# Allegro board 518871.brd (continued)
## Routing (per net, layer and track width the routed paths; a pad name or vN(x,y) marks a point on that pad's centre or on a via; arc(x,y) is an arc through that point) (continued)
H_DDR1_A12: length 100.4
  TOP w0.102: U29.N7 v2(11.11,76.11)
  TOP w0.127: v2(11.11,90.33) U23.N7 11.51,92.01 12.22,92.71 21.17,92.71 23.02,94.56 23.02,98.43 23.16,98.57 23.77,98.57 23.89,98.7 23.89,99.51 24.02,99.64 24.27,99.64 24.4,99.51 24.4,98.7 24.53,98.57 24.78,98.57 24.91,98.7 24.91,99.51 25.04,99.64 25.29,99.64 25.42,99.51 25.42,98.7 25.54,98.57 25.8,98.57 25.93,98.7 25.93,99.51 26.05,99.64 26.31,99.64 26.43,99.51 26.43,98.7 26.56,98.57 26.81,98.57 26.94,98.7 26.94,99.51 27.07,99.64 27.32,99.64 27.45,99.51 27.45,98.7 27.58,98.57 27.83,98.57 27.96,98.7 27.96,99.51 28.08,99.64 28.34,99.64 28.47,99.51 28.47,98.7 28.59,98.57 28.85,98.57 28.97,98.7 28.97,99.51 29.1,99.64 29.35,99.64 29.48,99.51 29.48,98.7 29.61,98.57 29.86,98.57 29.99,98.7 29.99,99.51 30.12,99.64 30.37,99.64 30.5,99.51 30.5,98.7 30.62,98.57 30.88,98.57 31.01,98.7 31.01,99.51 31.13,99.64 31.39,99.64 31.51,99.51 31.51,98.7 31.64,98.57 31.89,98.57 32.02,98.7 32.02,99.51 32.15,99.64 32.4,99.64 32.53,99.51 32.53,98.7 32.66,98.57 32.91,98.57 33.04,98.7 33.04,99.51 33.16,99.64 33.42,99.64 33.55,99.51 33.55,98.7 33.67,98.57 33.93,98.57 34.05,98.7 34.05,99.51 34.18,99.64 34.43,99.64 34.56,99.51 34.56,98.7 34.69,98.57 34.94,98.57 35.07,98.7 35.07,99.51 35.2,99.64 35.45,99.64 35.58,99.51 35.58,98.7 35.7,98.57 35.96,98.57 36.09,98.7 36.09,99.51 36.21,99.64 36.47,99.64 36.59,99.51 36.59,98.7 36.72,98.57 36.97,98.57 37.1,98.7 37.1,99.51 37.23,99.64 37.48,99.64 37.61,99.51 37.61,98.7 37.74,98.57 37.99,98.57 38.12,98.7 38.12,99.51 38.24,99.64 38.5,99.64 38.63,99.51 38.63,98.7 38.75,98.57 39.01,98.57 39.13,98.7 39.13,99.51 39.26,99.64 39.51,99.64 39.64,99.51 39.64,98.7 39.77,98.57 40.49,98.57 40.74,98.32 40.74,98.02 40.22,97.5 40.22,97.01 40.55,96.68 41.11,96.68 v1(41.3,96.88) ; U27.AC22 v3(43.35,88.87)
  LY3 w0.133: v1(41.3,96.88) 41.3,96.37 43.35,94.31 v3(43.35,88.87)
  LY4 w0.133: v2(11.11,90.33) 11.51,89.71 11.51,88.49 11.24,87.47 11.24,86.56 11.51,82.73 11.51,76.5 v2(11.11,76.11) 11.51,75.71 11.51,73.74 11.18,73.41 11.18,72.64 12.06,71.75 v1(12.06,70.36)
  BOTTOM w0.127: v1(12.06,70.36) R282.2
H_DDR1_A13: length 99
  TOP w0.102: U29.T3 v2(8.71,80.1) ; U23.T3 v2(8.71,94.33)
  TOP w0.127: U27.AC15 v3(48.55,88.87) ; R83.2 v1(4.7,69.91)
  LY3 w0.133: v1(4.7,69.91) 4.7,75.64 8.71,79.66 v2(8.71,80.1) 6.48,80.1 5.99,80.59 5.99,93.98 6.76,94.74 8.3,94.74 v2(8.71,94.33)
  LY4 w0.133: v2(8.71,94.33) 9.12,94.73 9.12,97.79 10.09,98.76 24.4,98.76 26.14,100.5 26.49,100.5 26.63,100.37 26.63,99.51 26.76,99.38 27.03,99.38 27.16,99.51 27.16,100.37 27.29,100.5 27.56,100.5 27.69,100.37 27.69,99.51 27.83,99.38 28.09,99.38 28.23,99.51 28.23,100.37 28.36,100.5 28.63,100.5 28.76,100.37 28.76,99.51 28.89,99.38 29.16,99.38 29.29,99.51 29.29,100.37 29.43,100.5 29.69,100.5 29.83,100.37 29.83,99.51 29.96,99.38 30.23,99.38 30.36,99.51 30.36,100.37 30.49,100.5 30.76,100.5 30.89,100.37 30.89,99.51 31.03,99.38 31.29,99.38 31.43,99.51 31.43,100.37 31.56,100.5 31.83,100.5 31.96,100.37 31.96,99.6 32.09,99.47 32.51,99.47 32.64,99.6 32.64,99.95 33.19,100.5 42.63,100.5 43.94,99.2 44.6,99.2 44.72,99.32 45.57,99.32 48.39,96.5 48.39,92.46 47.77,91.84 47.77,90.03 48.55,89.24 v3(48.55,88.87)
H_DDR1_A14: length 100.1
  TOP w0.102: U29.T7 v2(8.71,76.11) ; U23.T7 v2(8.71,90.33)
  TOP w0.127: v1(41.66,99.64) 40.19,101.11 36.3,101.11 36.18,101.23 36.18,101.73 36.05,101.85 35.79,101.85 35.67,101.73 35.67,101.23 35.54,101.11 35.29,101.11 35.16,101.23 35.16,101.73 35.03,101.85 34.78,101.85 34.65,101.73 34.65,101.23 34.52,101.11 34.27,101.11 34.14,101.23 34.14,101.73 34.02,101.85 33.76,101.85 33.64,101.73 33.64,101.23 33.51,101.11 33.25,101.11 33.13,101.23 33.13,101.73 33,101.85 32.75,101.85 32.62,101.73 32.62,101.23 32.49,101.11 32.24,101.11 32.11,101.23 32.11,101.73 31.98,101.85 31.73,101.85 31.6,101.73 31.6,101.23 31.48,101.11 31.22,101.11 31.1,101.23 31.1,101.73 30.97,101.85 30.71,101.85 30.59,101.73 30.59,101.23 30.46,101.11 30.21,101.11 30.08,101.23 30.08,101.73 29.95,101.85 29.7,101.85 29.57,101.73 29.57,101.23 29.44,101.11 29.19,101.11 29.06,101.23 29.06,101.73 28.94,101.85 28.68,101.85 28.56,101.73 28.56,101.23 28.43,101.11 28.17,101.11 28.05,101.23 28.05,101.73 27.92,101.85 27.67,101.85 27.54,101.73 27.54,101.23 27.41,101.11 27.16,101.11 27.03,101.23 27.03,101.73 26.9,101.85 26.65,101.85 26.52,101.73 26.52,101.23 26.4,101.11 26.14,101.11 26.02,101.23 26.02,101.73 25.89,101.85 25.63,101.85 25.51,101.73 25.51,101.23 25.38,101.11 25.13,101.11 25,101.23 25,101.73 24.87,101.85 24.62,101.85 24.49,101.73 24.49,101.23 24.36,101.11 24.11,101.11 23.98,101.23 23.98,101.73 23.86,101.85 23.6,101.85 23.48,101.73 23.48,101.23 23.35,101.11 22.62,101.11 22.21,100.7 22.21,94.47 20.96,93.22 9.53,93.22 9.11,92.81 U23.T7 ; v3(48.55,88.22) U27.AB15
  LY3 w0.133: v1(7.49,70.36) 7.49,74.88 v2(8.71,76.11) ; v1(41.66,99.64) 43.24,99.64 43.75,99.13 44.54,99.13 44.69,99.28 46.77,99.28 49,97.05 49,88.66 v3(48.55,88.22)
  BOTTOM w0.127: v2(8.71,76.11) 7.85,76.97 7.85,77.42 6.82,78.75 6.82,87.92 v2(8.71,90.33) ; v1(7.49,70.36) R286.2
H_DDR1_A15: length 96.3
  TOP w0.102: U23.M7 v2(11.91,90.33) ; U29.M7 v2(11.91,76.11)
  TOP w0.127: v1(42.8,96.67) 41.94,96.67 41.66,96.39 40.26,96.39 39.73,96.92 39.73,97.28 39.6,97.41 39.2,97.41 39.07,97.28 39.07,97.15 38.95,97.03 38.69,97.03 38.56,97.15 38.56,97.88 38.44,98 38.18,98 38.06,97.88 38.06,97.15 37.93,97.03 37.68,97.03 37.55,97.15 37.55,97.88 37.42,98 37.17,98 37.04,97.88 37.04,97.15 36.91,97.03 36.66,97.03 36.53,97.15 36.53,97.88 36.41,98 36.15,98 36.02,97.88 36.02,97.15 35.9,97.03 35.64,97.03 35.52,97.15 35.52,97.88 35.39,98 35.14,98 35.01,97.88 35.01,97.15 34.88,97.03 34.63,97.03 34.5,97.15 34.5,97.88 34.37,98 34.12,98 33.99,97.88 33.99,97.15 33.87,97.03 33.61,97.03 33.48,97.15 33.48,97.88 33.36,98 33.1,98 32.98,97.88 32.98,97.15 32.85,97.03 32.6,97.03 32.47,97.15 32.47,97.88 32.34,98 32.09,98 31.96,97.88 31.96,97.15 31.83,97.03 31.58,97.03 31.45,97.15 31.45,97.88 31.33,98 31.07,98 30.94,97.88 30.94,97.15 30.82,97.03 30.56,97.03 30.44,97.15 30.44,97.88 30.31,98 30.06,98 29.93,97.88 29.93,97.15 29.8,97.03 29.55,97.03 29.42,97.15 29.42,97.88 29.29,98 29.04,98 28.91,97.88 28.91,97.15 28.79,97.03 28.53,97.03 28.4,97.15 28.4,97.88 28.28,98 28.02,98 27.9,97.88 27.9,97.15 27.77,97.03 27.52,97.03 27.39,97.15 27.39,97.88 27.26,98 27.01,98 26.88,97.88 26.88,97.15 26.75,97.03 26.5,97.03 26.37,97.15 26.37,97.88 26.25,98 25.99,98 25.86,97.88 25.86,97.15 25.74,97.03 25.48,97.03 25.36,97.15 25.36,97.88 25.23,98 24.98,98 24.85,97.88 24.85,97.15 24.72,97.03 24.47,97.03 24.34,97.15 24.34,97.88 24.21,98 23.96,98 23.83,97.88 23.83,97.51 23.36,97.04 23.36,94.54 21.28,92.46 12.45,92.46 12.03,92.04 12.03,91.86 12.16,91.73 12.62,91.73 12.79,91.56 12.79,91.16 12.36,90.73 U23.M7 ; U27.AC16 v3(47.25,88.87)
  LY4 w0.133: v3(47.25,88.87) 46.89,89.23 46.89,94.21 44.42,96.67 v1(42.8,96.67) ; v2(11.91,90.33) 12.31,89.71 12.31,88.17 11.87,85.39 11.87,83.16 12.31,81.95 12.31,77.33 v2(11.91,76.11) 12.31,75.71 12.31,72.52 13.21,71.63 v1(13.21,70.36)
  BOTTOM w0.127: v1(13.21,70.36) R281.2
H_DDR1_BA0: length 103.6
  TOP w0.102: U29.M2 v2(11.91,80.9) ; U23.M2 v2(11.91,95.13)
  TOP w0.127: v1(45.54,97.43) 46.41,97.43 47.14,96.7 47.14,95.15 46.66,94.67 46.66,93.19 47.46,92.39 47.46,92.13 47.46,90.7 47.58,90.58 U27.AE16
  LY3 w0.133: v1(45.54,97.43) 47.19,97.43 47.75,96.88 47.75,94.61 47.34,94.2 46.96,94.2 46.63,93.88 46.63,93.7 46.46,93.52 45.73,93.52 45.6,93.66 45.6,94.44 45.92,94.77 47.04,94.77 47.27,95 47.27,96.42 46.79,96.9 45.22,96.9 45.09,97.03 45.09,97.38 44.8,97.67 43.59,97.67 43.08,98.18 40.84,98.18 38.96,100.06 34.25,100.06 33.43,100.88 29.57,100.88 28.8,100.11 16.49,100.11 16.35,99.98 16.35,98.96 16.22,98.83 15.95,98.83 15.82,98.96 15.82,99.98 15.69,100.11 15.42,100.11 15.29,99.98 15.29,98.96 15.15,98.83 14.89,98.83 14.75,98.96 14.75,99.98 14.62,100.11 14.35,100.11 14.22,99.98 14.22,98.96 14.09,98.83 13.82,98.83 13.69,98.96 13.69,99.98 13.55,100.11 13.28,100.11 12.77,99.6 12.77,98.9 11.84,97.97 11.84,96.75 12.4,96.19 12.4,95.61 v2(11.91,95.13) 12.32,94.73 12.32,94.16 13.03,93.45 14.2,93.45 14.61,93.04 14.61,91.57 14.15,91.11 12.01,91.11 11.51,90.61 11.51,88.36 12.11,87.77 12.11,86.2 11.9,85.99 11.9,84.79 12.78,83.91 12.78,81.77 v2(11.91,80.9) 12.31,80.5 12.31,74.94 14.35,72.9 v1(14.35,70.36)
  BOTTOM w0.127: v1(14.35,70.36) R280.2
H_DDR1_BA1: length 93.1
  TOP w0.102: U29.N8 v2(11.11,75.31)
  TOP w0.127: v2(11.11,89.53) U23.N8 ; v3(47.25,87.57) U27.AA16 ; R89.2 v1(11.56,69.91)
  LY4 w0.133: v1(11.56,69.91) 11.56,71.75 10.71,72.6 10.71,74.9 v2(11.11,75.31) 10.72,75.7 10.72,76.56 10.31,76.96 8.64,76.96 8.31,77.29 8.31,86.29 8.44,86.42 8.99,86.42 9.12,86.56 9.12,86.82 8.99,86.96 8.44,86.96 8.31,87.09 8.31,87.35 8.86,87.91 10.15,87.91 10.71,88.47 10.71,89.13 v2(11.11,89.53) 10.72,89.93 10.72,92.64 9.91,93.44 9.91,97.9 10.43,98.42 24.74,98.42 25.45,99.12 26.65,99.12 26.65,99.12 33.06,99.12 33.4,99.45 33.4,99.69 33.89,100.19 34.62,100.19 34.75,100.05 34.75,99.43 34.89,99.3 35.15,99.3 35.29,99.43 35.29,100.05 35.42,100.19 35.69,100.19 35.82,100.05 35.82,99.43 35.95,99.3 36.22,99.3 36.35,99.43 36.35,100.05 36.49,100.19 36.75,100.19 36.89,100.05 36.89,99.43 37.02,99.3 37.29,99.3 37.42,99.43 37.42,100.05 37.55,100.19 37.82,100.19 37.95,100.05 37.95,99.43 38.09,99.3 38.35,99.3 38.49,99.43 38.49,100.05 38.62,100.19 42.18,100.19 43.31,99.06 43.31,98.81 43.75,98.36 46.04,98.36 48.01,96.4 48.01,93.05 47.5,92.54 47.5,89.67 48.01,89.16 48.01,88.32 v3(47.25,87.57)
H_DDR1_BA2: length 101.8
  TOP w0.102: U23.M3 v2(11.91,94.33) ; U29.M3 v2(11.91,80.1)
  TOP w0.127: R91.2 v1(13.84,69.91) ; U27.AB16 v3(47.25,88.22)
  LY4 w0.133: v2(11.91,94.33) 11.91,93.72 11.47,93.27 10.95,93.27 10.72,93.5 10.72,96.24 11.22,96.74 11.22,97.83 11.54,98.16 25.08,98.16 25.7,98.78 28.9,98.78 29.03,98.64 29.03,98.13 29.17,98 29.43,98 29.57,98.13 29.57,98.64 29.7,98.78 29.97,98.78 30.1,98.64 30.1,98.13 30.23,98 30.5,98 30.63,98.13 30.63,98.64 30.77,98.78 31.03,98.78 31.17,98.64 31.17,98.13 31.3,98 31.57,98 31.7,98.13 31.7,98.64 31.83,98.78 32.1,98.78 32.23,98.64 32.23,98.13 32.37,98 32.63,98 32.77,98.13 32.77,98.64 32.9,98.78 33.17,98.78 33.3,98.64 33.3,98.13 33.43,98 33.7,98 33.83,98.13 33.83,98.64 33.97,98.78 34.23,98.78 34.37,98.64 34.37,98.13 34.5,98 34.77,98 34.9,98.13 34.9,98.64 35.03,98.78 35.3,98.78 35.43,98.64 35.43,98.13 35.57,98 35.83,98 35.97,98.13 35.97,98.64 36.1,98.78 36.37,98.78 36.5,98.64 36.5,98.13 36.63,98 36.9,98 37.03,98.13 37.03,98.64 37.17,98.78 37.43,98.78 37.57,98.64 37.57,98.13 37.7,98 37.97,98 38.1,98.13 38.1,98.64 38.23,98.78 38.68,98.78 39.75,99.84 40.72,99.84 42.59,97.97 45.92,97.97 47.62,96.27 47.62,93.19 47.19,92.76 47.19,89.47 47.64,89.02 47.64,88.6 v3(47.25,88.22)
  BOTTOM w0.127: v2(11.91,94.33) 11.91,93.88 12.31,93.48 12.31,88.57 12.08,88.34 11.91,88.34 10.92,87.35 10.92,87.17 11.3,86.79 11.3,86.61 11.12,86.43 10.94,86.43 10.56,86.81 10.38,86.81 9.68,86.11 9.68,85.85 9.8,85.73 10.21,85.73 10.34,85.6 10.34,85.34 10.21,85.22 9.8,85.22 9.68,85.09 9.68,84.62 9.8,84.49 10.29,84.49 10.41,84.36 10.41,84.11 10.29,83.98 9.8,83.98 9.68,83.85 9.68,83.6 9.8,83.47 10.11,83.47 10.24,83.35 10.24,83.09 10.11,82.96 9.8,82.96 9.68,82.84 9.68,82.58 10.16,82.1 10.48,82.1 10.71,81.87 10.71,81.55 10.96,81.3 11.28,81.3 11.51,81.07 11.51,80.75 11.53,80.73 11.53,80.49 v2(11.91,80.1) 11.91,79.02 9.92,77.03 9.92,73.95 11.79,72.09 12.47,72.09 13.84,70.71 v1(13.84,69.91)
H_DDR1_CASN: length 110.2
  TOP w0.102: U23.K3 v2(13.51,94.33) ; U27.AD16 47.9,89.51 47.9,90.02 47.83,90.09 47.83,90.58 ; U29.K3 v2(13.51,80.1)
  TOP w0.127: 47.83,90.58 47.83,90.72 47.71,90.84 47.71,93.5 47.5,93.72 47.5,97.66 44.87,100.29 v1(44.59,100.29) ; v1(18.41,69.91) R95.2
  LY4 w0.133: v2(13.51,80.1) 13.51,76.86 13.91,76.46 13.91,73.59 15.54,71.96 17.19,71.96 18.41,70.73 v1(18.41,69.91)
  BOTTOM w0.127: v1(44.59,100.29) 44.03,100.29 43.83,100.09 41.16,100.09 40.92,99.85 40.92,99.61 40.79,99.48 40.54,99.48 40,98.94 34.75,98.94 34.5,99.19 34.5,99.89 34.37,100.02 34.1,100.02 33.97,99.89 33.97,99.04 33.84,98.92 33.59,98.92 33.46,99.04 33.46,99.96 33.33,100.09 33.08,100.09 32.95,99.96 32.95,99.04 32.83,98.92 32.57,98.92 32.45,99.04 32.45,99.96 32.32,100.09 32.06,100.09 31.94,99.96 31.94,99.04 31.81,98.92 31.56,98.92 31.43,99.04 31.43,99.96 31.3,100.09 31.05,100.09 30.92,99.96 30.92,99.04 30.79,98.92 30.54,98.92 30.41,99.04 30.41,99.96 30.29,100.09 30.03,100.09 29.91,99.96 29.91,99.04 29.78,98.92 29.52,98.92 29.4,99.04 29.4,99.96 29.27,100.09 29.02,100.09 28.89,99.96 28.89,99.04 28.76,98.92 28.51,98.92 28.38,99.04 28.38,99.96 28.25,100.09 28,100.09 27.87,99.96 27.87,99.04 27.75,98.92 27.49,98.92 27.37,99.04 27.37,99.96 27.24,100.09 26.98,100.09 26.86,99.96 26.86,99.04 26.73,98.92 26.48,98.92 26.35,99.04 26.35,99.96 26.22,100.09 25.97,100.09 25.84,99.96 25.84,99.04 25.71,98.92 25.46,98.92 25.33,99.04 25.33,99.96 25.21,100.09 24.95,100.09 24.83,99.96 24.83,99.04 24.7,98.92 24.44,98.92 24.32,99.04 24.32,99.96 24.19,100.09 23.94,100.09 23.81,99.96 23.81,99.04 23.68,98.92 23.43,98.92 23.3,99.04 23.3,99.96 23.14,100.12 16.5,100.12 16.37,100 16.37,97.19 16.16,96.98 14.29,96.98 13.91,96.6 13.91,94.72 v2(13.51,94.33) 14.93,92.91 17.37,92.91 17.73,92.56 17.73,92 17.42,91.69 15.01,91.69 13.92,90.6 13.92,89.37 14.15,89.14 14.35,88.93 14.35,86.66 13.77,86.08 13.77,84.71 15.09,83.39 15.09,82.24 13.92,81.07 13.92,80.51 v2(13.51,80.1)
H_DDR1_CKE: length 92.6
  TOP w0.102: U29.K9 v2(13.51,74.51) ; U23.K9 v2(13.51,88.73)
  TOP w0.127: U27.AB18 v3(46.6,88.22)
  LY3 w0.133: v2(13.51,74.51) 13.2,74.51 12.67,75.03 12.67,75.51 13.11,75.94 13.11,76.27 12.67,76.7 12.67,77.37 12.81,77.5 13.38,77.5 13.51,77.64 13.51,77.9 13.38,78.04 12.81,78.04 12.67,78.17 12.67,78.58 12.93,78.83 12.93,79.02 12.92,79.03 12.92,79.22 13.11,79.41 13.3,79.41 13.31,79.4 13.5,79.4 13.92,79.82 13.92,81.48 15.24,82.8 15.24,83.24 13.82,84.66 13.82,85.55 14.1,85.83 14.1,87.17 14.64,87.71 14.64,88.36 14.27,88.73 v2(13.51,88.73)
  LY4 w0.133: v3(46.6,88.22) 46.08,88.75 46.08,91.34 45.09,92.33 45.09,92.96 45.47,93.34 45.47,94.11 44.7,94.87 43.05,94.87 41.91,96.01 40.64,96.01 40.01,96.65 39,96.65 38.68,96.32 38.41,96.32 38.28,96.45 38.28,97.16 38.14,97.29 37.88,97.29 37.74,97.16 37.74,96.45 37.61,96.32 37.34,96.32 37.21,96.45 37.21,97.16 37.08,97.29 36.81,97.29 36.68,97.16 36.68,96.45 36.54,96.32 36.28,96.32 36.14,96.45 36.14,97.16 36.01,97.29 35.74,97.29 35.61,97.16 35.61,96.45 35.48,96.32 35.21,96.32 35.08,96.45 35.08,97.16 34.94,97.29 34.68,97.29 34.54,97.16 34.54,96.45 34.41,96.32 34.14,96.32 34.01,96.45 34.01,97.16 33.88,97.29 33.61,97.29 33.48,97.16 33.48,96.45 33.34,96.32 33.08,96.32 32.94,96.45 32.94,97.16 32.81,97.29 32.54,97.29 32.41,97.16 32.41,96.45 32.28,96.32 32.01,96.32 31.88,96.45 31.88,97.16 31.74,97.29 31.48,97.29 31.34,97.16 31.34,96.45 31.21,96.32 30.94,96.32 30.81,96.45 30.81,97.16 30.68,97.29 30.41,97.29 30.28,97.16 30.28,96.45 30.14,96.32 29.88,96.32 29.74,96.45 29.74,97.16 29.61,97.29 29.34,97.29 29.21,97.16 29.21,96.45 29.08,96.32 28.81,96.32 28.68,96.45 28.68,97.16 28.54,97.29 28.28,97.29 28.14,97.16 28.14,96.45 28.01,96.32 23.31,96.32 22.7,96.94 15.27,96.94 14.86,96.52 13.35,96.52 13.11,96.28 13.11,91.43 13.91,90.63 13.91,89.13 v2(13.51,88.73) ; v1(15.49,70.36) 15.05,70.8 15.05,71.82 13.51,73.35 v2(13.51,74.51)
  BOTTOM w0.127: v1(15.49,70.36) R279.2
H_DDR1_CLK_N: length 106.9
  TOP w0.102: U27.AE21 44.33,90.7 44.27,90.76 44.27,91.48
  TOP w0.103: U29.K7 v2(13.51,76.11) ; U23.K7 v2(13.51,90.33)
  TOP w0.112: 44.27,91.48 42.06,93.69 39.79,93.69 39.74,93.73 39.09,93.73 38.86,93.96 38.86,94.62 38.1,95.38 36.96,95.38 36.42,94.83 36.42,94.54 36.3,94.43 35.87,94.43 34.95,95.35 32.46,95.35 32.13,95.02 32.13,93.57 32.45,93.25 32.95,93.25 33.07,93.14 33.07,92.92 32.95,92.8 32.45,92.8 32.13,92.48 32.13,91.97 32.45,91.65 32.95,91.65 33.07,91.53 33.07,91.31 32.95,91.2 32.45,91.2 32.13,90.88 32.13,89.65 32.01,89.54 31.74,89.54 31.63,89.65 31.63,95.29 31.31,95.61 30.73,95.61 30.37,95.25 30.37,92.15 30.26,92.04 30.03,92.04 29.92,92.15 29.92,95.32 29.6,95.64 29.01,95.64 28.69,95.32 28.69,91.89 28.58,91.78 28.32,91.78 28.21,91.89 28.21,95.33 27.89,95.65 27.36,95.65 27.04,95.33 27.04,91.67 26.92,91.56 26.66,91.56 26.55,91.67 26.55,95.33 26.23,95.65 25.67,95.65 25.35,95.33 25.35,91.78 25.24,91.66 25,91.66 24.89,91.78 24.89,93.84 24.57,94.16 24.05,94.16 23.73,93.84 23.73,92.38 23.12,91.78 14.29,91.78 13.91,91.4 U23.K7
  LY3 w0.114: v2(13.51,90.33) 13.9,89.94 14.58,89.94 14.76,89.76 14.76,88.81 15.34,88.22 15.34,87.85 14.5,87.02 14.5,85.7 14.88,85.32 14.88,84.26 15.88,83.27 15.88,82.85 14.94,81.92 14.94,80.11 13.73,78.91 13.73,78.45 14.33,77.86 14.33,77.67 13.51,76.86 13.51,76.18 13.51,76.18 v2(13.51,76.11) 13.9,75.72 14.58,75.72 14.94,75.36 14.94,74.29 16.14,73.09 16.14,70.85 v1(16.64,70.36)
  BOTTOM w0.127: v1(16.64,70.36) R278.2
H_DDR1_CLK_P: length 106.5
  TOP w0.102: U27.AD21 44.33,89.39 44.01,89.71 44.01,90.56 43.94,90.62 43.94,91.28
  TOP w0.103: U23.J7 v2(14.31,90.33) ; U29.J7 v2(14.31,76.11)
  TOP w0.112: U23.J7 14.48,90.73 14.27,90.94 14.27,91.26 14.44,91.42 23.27,91.42 24.08,92.24 24.08,93.7 24.2,93.81 24.42,93.81 24.53,93.7 24.53,91.63 24.85,91.31 25.38,91.31 25.7,91.63 25.7,95.18 25.82,95.3 26.08,95.3 26.2,95.18 26.2,91.52 26.52,91.2 27.07,91.2 27.39,91.52 27.39,95.18 27.5,95.3 27.74,95.3 27.85,95.18 27.85,91.75 28.17,91.43 28.73,91.43 29.05,91.75 29.05,95.17 29.16,95.29 29.45,95.29 29.56,95.17 29.56,92.01 29.88,91.69 30.41,91.69 30.73,92.01 30.73,95.1 30.88,95.26 31.17,95.26 31.28,95.14 31.28,89.51 31.6,89.19 32.16,89.19 32.48,89.51 32.48,90.73 32.59,90.84 33.1,90.84 33.42,91.16 33.42,91.68 33.1,92 32.59,92 32.48,92.11 32.48,92.34 32.59,92.45 33.1,92.45 33.42,92.77 33.42,93.29 33.1,93.61 32.59,93.61 32.48,93.72 32.48,94.87 32.61,95 34.8,95 35.72,94.07 36.45,94.07 36.77,94.39 36.77,94.68 37.11,95.02 37.95,95.02 38.5,94.47 38.5,93.81 38.94,93.38 39.6,93.38 39.64,93.33 41.91,93.33 43.94,91.3 43.94,91.28
  TOP w0.127: R94.2 v1(17.27,69.91)
  LY3 w0.114: v1(17.27,69.91) 17.27,70.36 16.5,71.13 16.5,73.24 15.3,74.44 15.3,75.51 14.7,76.11 v2(14.31,76.11) 14.09,76.11 13.87,76.33 13.87,76.71 14.68,77.53 14.68,78 14.09,78.6 14.09,78.76 15.29,79.97 15.29,81.77 16.23,82.71 16.23,83.41 15.24,84.4 15.24,85.47 14.86,85.85 14.86,86.87 15.7,87.71 15.7,88.37 15.11,88.96 15.11,89.94 14.73,90.33 v2(14.31,90.33)
H_DDR1_CSN0: length 106.5
  TOP w0.102: U27.AC19 45.31,88.87 45.31,90.58 ; U29.L2 v2(12.71,80.9)
  TOP w0.127: 45.31,90.58 45.31,91.68 43.87,93.12 43.87,95.28 44.15,95.55 v1(44.15,95.99) ; R93.2 v1(16.13,69.91) ; U23.L2 v2(12.71,95.13)
  LY3 w0.133: v2(12.71,80.9) 13.12,81.31 13.12,81.87 13.35,82.1 13.91,82.1 14.68,82.87 14.68,83.21 13.41,84.48 13.41,85.85 13.77,86.21 13.77,87.91 13.12,88.56 13.12,90.49 13.35,90.73 14.53,90.73 14.59,90.78 14.66,90.78 15.01,91.13 15.01,93.55 14.68,93.88 13.33,93.88 13.11,94.1 U23.L2 v2(12.71,95.13) 12.71,97.26 12.87,97.41 12.87,98.11 13.25,98.5 16.6,98.5 16.84,98.73 16.84,99.38 17.08,99.63 18.84,99.63 18.97,99.49 18.97,99.01 19.1,98.88 19.37,98.88 19.5,99.01 19.5,99.49 19.64,99.63 22.65,99.63 22.79,99.49 22.79,98.87 22.92,98.74 23.19,98.74 23.32,98.87 23.32,99.49 23.45,99.63 23.72,99.63 23.85,99.49 23.85,98.87 23.99,98.74 24.25,98.74 24.39,98.87 24.39,99.49 24.52,99.63 24.79,99.63 24.92,99.49 24.92,98.87 25.05,98.74 25.32,98.74 25.45,98.87 25.45,99.49 25.59,99.63 25.85,99.63 25.99,99.49 25.99,98.87 26.12,98.74 26.39,98.74 26.52,98.87 26.52,99.49 26.65,99.63 26.92,99.63 27.05,99.49 27.05,98.87 27.19,98.74 27.45,98.74 27.59,98.87 27.59,99.49 27.72,99.63 27.99,99.63 28.12,99.49 28.12,98.87 28.25,98.74 28.52,98.74 28.65,98.87 28.65,99.49 28.79,99.63 29.47,99.63 29.6,99.76 29.6,100.28 29.74,100.41 30,100.41 30.14,100.28 30.14,99.76 30.27,99.63 30.54,99.63 30.67,99.76 30.67,100.28 30.8,100.41 31.07,100.41 31.2,100.28 31.2,99.76 31.34,99.63 31.6,99.63 31.74,99.76 31.74,100.28 31.87,100.41 32.14,100.41 32.27,100.28 32.27,99.76 32.4,99.63 32.67,99.63 32.8,99.76 32.8,100.28 32.94,100.41 33.2,100.41 33.34,100.28 33.34,99.76 33.47,99.63 33.76,99.63 33.89,99.49 33.89,98.82 34.02,98.69 34.29,98.69 34.42,98.82 34.42,99.49 34.56,99.63 34.82,99.63 34.96,99.49 34.96,98.82 35.09,98.69 35.36,98.69 35.49,98.82 35.49,99.49 35.62,99.63 35.89,99.63 36.02,99.49 36.02,98.82 36.16,98.69 36.42,98.69 36.56,98.82 36.56,99.49 36.69,99.63 36.96,99.63 37.09,99.49 37.09,98.82 37.22,98.69 37.49,98.69 37.62,98.82 37.62,99.49 37.76,99.63 38.83,99.63 40.53,97.92 42.82,97.92 43.28,97.46 43.28,96.52 43.41,96.39 43.73,96.39 43.87,96.53 43.87,97.2 44,97.33 44.59,97.33 44.72,97.2 44.72,96.12 44.59,95.99 v1(44.15,95.99)
  BOTTOM w0.127: v1(16.13,69.91) 16.13,70.48 15.82,70.8 14.38,70.8 11.59,73.58 11.28,73.58 10.72,74.14 10.72,77.34 12.32,78.94 12.32,80.27 12.71,80.66 v2(12.71,80.9)
H_DDR1_D0: length 33.2
  TOP w0.102: U23.H7 v2(15.91,90.33)
  TOP w0.127: U27.AA23 v3(42.7,87.57)
  LY3 w0.133: v3(42.7,87.57) 40.14,87.57 40,87.7 40,88 39.87,88.14 39.6,88.14 39.47,88 39.47,87.7 39.34,87.57 39.07,87.57 38.94,87.7 38.94,88 38.8,88.14 38.54,88.14 38.4,88 38.4,87.7 38.27,87.57 38.04,87.57 37.49,88.12 32.99,88.12 31.97,89.13 30.37,89.13 29.46,90.04 28.85,90.04 27.91,89.1 27.53,89.1 26.64,89.99 26.11,89.99 25.22,89.1 24.99,89.1 24.16,89.94 23.75,89.94 22.95,89.13 16.5,89.13 16.31,89.32 16.31,89.93 v2(15.91,90.33)
H_DDR1_D1: length 34
  TOP w0.102: 42.18,88.54 42.05,88.67 42.05,88.68 41.86,88.86 41.49,88.86 41.43,88.8 ; U23.F8 v2(17.51,89.53)
  TOP w0.103: 42.18,88.54 U27.AC24
  TOP w0.127: 41.43,88.8 35.71,88.8 35.55,88.96 34.81,88.96 v1(34.44,88.6)
  LY3 w0.133: v2(17.51,89.53) 17.91,89.93 22.03,89.93 22.53,90.42 29.77,90.42 30.65,89.54 33.3,89.54 33.43,89.67 33.43,89.86 33.3,89.99 30.97,89.99 30.84,90.12 30.84,90.31 30.97,90.44 34.14,90.44 34.44,90.14 v1(34.44,88.6)
H_DDR1_D2: length 30.8
  TOP w0.102: 40.97,88.21 42.06,88.21 U27.AB24 ; U23.F7 v2(17.51,90.33)
  TOP w0.127: 40.97,88.21 35.94,88.21 35.84,88.11 34.19,88.11 33.76,88.54 v1(33.22,88.54)
  LY4 w0.133: v1(33.22,88.54) 29.01,92.76 27.99,92.76 27.59,92.36 27.59,92.11 27.46,91.97 27.2,91.97 27.06,92.11 27.06,92.63 26.93,92.76 26.67,92.76 26.54,92.63 26.54,92.44 26.4,92.3 26.14,92.3 26.01,92.44 26.01,92.63 25.88,92.76 19.02,92.76 17.51,91.25 v2(17.51,90.33)
H_DDR1_D3: length 34.3
  TOP w0.102: 41.76,90.58 42.05,90.28 42.05,89.68 42.38,89.35 U27.AD24 ; U23.H8 v2(15.91,89.53)
  TOP w0.127: 41.76,90.58 41.63,90.7 40.64,90.7 39.52,89.58 36.18,89.58 34.75,91.01 v1(34.75,91.74)
  LY3 w0.133: v1(34.75,91.74) 34.35,91.35 17.67,91.35 16.33,92.68 15.64,92.68 15.43,92.48 15.43,90.44 15.49,90.37 15.49,89.95 v2(15.91,89.53)
H_DDR1_D4: length 33.1
  TOP w0.102: U23.E3 v2(18.31,94.33)
  TOP w0.127: U27.AB23 v3(42.7,88.22)
  LY3 w0.133: v2(18.31,94.33) 18.71,94.73 31.97,94.73 33.02,93.68 34.62,93.68 36.45,95.5 37.72,95.5 38.61,94.61 41.99,94.61 42.34,94.26 42.34,93.78 42.7,93.41 v3(42.7,88.22)
H_DDR1_D5: length 34.6
  TOP w0.102: 41.13,89.52 40.94,89.33 40.73,89.33 ; U23.H3 v2(15.91,94.33)
  TOP w0.103: 41.13,89.52 41.88,89.52 42.05,89.34 42.05,89.06 42.24,88.87 42.71,88.87 U27.AC23
  TOP w0.127: v1(33.83,93.01) 33.83,90.68 35.04,89.47 35.87,89.47 36.02,89.32 40.73,89.32 40.73,89.33
  LY3 w0.133: v2(15.91,94.33) 16.31,94.73 17.72,94.73 17.91,94.53 17.91,94.07 18.21,93.78 23.19,93.78 23.57,94.16 31.87,94.16 32.08,93.95 32.08,93.76 31.87,93.56 31.41,93.56 31.27,93.42 31.27,93.12 31.37,93.01 v1(33.83,93.01)
H_DDR1_D6: length 34.5
  TOP w0.102: U23.F2 v2(17.51,95.13) ; U27.AD23 42.7,89.52 42.7,90.58
  TOP w0.127: 42.7,90.58 42.7,90.67 42.08,91.29 40.53,91.29 38.73,93.09 35.94,93.09 34.47,94.56 v1(32.89,94.56)
  LY3 w0.133: v2(17.51,95.13) 17.91,95.53 23.77,95.53 24.03,95.78 24.03,95.98 24.21,96.16 34.67,96.16 34.8,96.03 34.8,95.69 34.67,95.55 33.32,95.55 32.89,95.12 v1(32.89,94.56)
H_DDR1_D7: length 34.3
  TOP w0.102: U23.G2 v2(16.71,95.13)
  TOP w0.127: v1(34.12,94.12) 35.53,92.71 38.63,92.71 40.38,90.96 42.01,90.96 42.38,90.59 U27.AE24
  LY3 w0.133: v2(16.71,95.13) 17.11,95.53 17.11,96.18 17.4,96.47 35.5,96.47 35.69,96.29 35.69,95.63 35.18,95.12 34.42,95.12 34.12,94.83 v1(34.12,94.12)
H_DDR1_D8: length 31.2
  TOP w0.102: U23.A2 v2(21.51,95.13) ; 40.97,87.57 42.05,87.57 U27.AA24
  TOP w0.127: v1(37.31,87.45) 37.7,87.45 37.82,87.57 40.97,87.57
  LY4 w0.133: v1(37.31,87.45) 37.31,88.44 37.18,88.57 36.68,88.57 36.55,88.7 36.55,88.97 36.68,89.1 37.31,89.1 37.47,89.26 37.47,89.46 37.27,89.66 36.32,89.66 35.94,90.04 35.94,90.42 35.81,90.55 35.33,90.55 35.15,90.73 35.15,91.13 35.02,91.26 34.62,91.26 34.24,91.64 34.24,92.51 34.52,92.79 34.52,93.4 34.34,93.57 33.91,93.57 33.6,93.88 33.6,94.84 33.32,95.13 32.57,95.13 32.44,95 32.44,94.44 32.3,94.31 32.11,94.31 31.98,94.44 31.98,95 31.85,95.13 v2(21.51,95.13)
H_DDR1_D9: length 33.5
  TOP w0.102: U23.B8 v2(20.71,89.53)
  TOP w0.127: U27.W25 41.64,85.85 41.09,85.85 41.08,85.87 37.85,85.87 37.81,85.91 37.29,85.91 36.53,85.14 34.8,85.14 34.1,85.84 34.1,86.42 33.59,86.93 31.43,86.93 31.11,87.25 31.11,87.63 30.85,87.9 30.59,87.9 30.32,88.17 30.32,90.53 30.01,90.84 29.38,90.84 29.05,90.51 29.05,88.13 28.88,87.96 28.63,87.96 28.5,88.09 28.5,90.2 28.37,90.32 28.12,90.32 27.97,90.17 27.97,89.08 27.53,88.65 v1(27.03,88.65)
  LY4 w0.133: v1(27.03,88.65) 26.54,89.13 26.28,89.13 26.13,89.28 26.13,89.51 25.97,89.66 25.75,89.66 25.59,89.51 25.59,89.28 25.44,89.13 21.11,89.13 v2(20.71,89.53)
H_DDR1_D10: length 39
  TOP w0.102: U27.Y23 42.7,86.27 42.06,86.27 ; U23.A7 v2(21.51,90.33)
  TOP w0.103: 40.97,86.27 42.06,86.27
  TOP w0.127: v2(21.51,90.33) 21.6,90.25 22.35,90.25 22.83,90.73 23.75,90.73 23.88,90.6 23.88,89.41 24.01,89.28 24.21,89.28 24.33,89.41 24.33,90.67 24.52,90.86 24.77,90.86 24.9,90.73 24.9,89.41 25.02,89.28 25.28,89.28 25.41,89.41 25.41,90.7 25.53,90.83 25.79,90.83 25.91,90.7 25.91,89.36 26.04,89.23 26.22,89.23 26.35,89.36 26.35,90.63 26.55,90.83 26.8,90.83 26.93,90.7 26.93,89.33 27.06,89.2 27.31,89.2 27.44,89.33 27.44,90.6 27.56,90.73 28.51,90.73 29.09,91.31 30.49,91.31 30.76,91.04 30.76,88.5 31.24,88.01 33.65,88.01 34.04,87.63 34.04,87.12 34.29,86.87 34.67,86.87 34.92,86.61 34.92,85.72 35.18,85.47 36.35,85.47 37.04,86.16 38.52,86.16 38.63,86.27 40.97,86.27
H_DDR1_D11: length 31.9
  TOP w0.102: U23.C8 v2(19.91,89.53)
  TOP w0.127: U27.AD25 41.31,89.19 41.19,89.07 35.83,89.07 35.69,89.22 33.06,89.22 32.38,88.54 v1(31.85,88.54)
  LY4 w0.133: v1(31.85,88.54) 30.51,88.54 30.38,88.68 30.38,90.55 30.1,90.83 29.73,90.83 29.18,90.28 29,90.28 28.81,90.47 28.81,90.65 29.36,91.2 29.36,91.39 29.11,91.64 23.55,91.64 22.81,92.38 19.2,92.38 18.71,91.89 18.71,90.1 18.89,89.93 19.52,89.93 v2(19.91,89.53)
H_DDR1_D12: length 31.2
  TOP w0.102: U23.C3 v2(19.91,94.33)
  TOP w0.127: v1(35.36,88.54) U27.AC25
  LY4 w0.133: v1(35.36,88.54) 35.77,88.96 35.77,89.27 35.64,89.41 35.44,89.41 34.79,90.05 34.61,90.05 34.45,89.89 34.45,89.41 34.32,89.28 34.09,89.28 33.96,89.41 33.96,90.01 33.51,90.46 33.51,92.22 33.39,92.34 33.13,92.34 33.02,92.23 33.02,91.54 32.94,91.47 32.64,91.47 32.54,91.57 32.54,93.37 32.26,93.65 31.32,93.65 30.56,94.41 27.86,94.41 27.1,93.65 20.04,93.65 19.91,93.78 v2(19.91,94.33)
H_DDR1_D13: length 31.5
  TOP w0.102: U23.D7 v2(19.11,90.33)
  TOP w0.127: U27.AB25 36.65,87.89 36.54,87.78 35.33,87.78 35.21,87.67 v1(35.2,87.67)
  LY4 w0.133: v1(35.2,87.67) 34.76,87.67 34.67,87.76 31.16,87.76 30.72,88.19 30.46,88.19 30.15,87.88 30.15,87.71 30,87.55 29.72,87.55 29.6,87.67 29.6,88.1 29.49,88.21 29.24,88.21 29.11,88.08 29.11,87.46 28.98,87.33 28.22,87.33 28.09,87.46 28.09,87.71 28.55,88.16 28.55,89.53 26.8,91.29 23.02,91.29 22.89,91.42 22.89,91.77 22.58,92.08 22.3,92.08 22,91.77 21.46,91.77 21.16,92.08 20.8,92.08 20.45,91.72 20.02,91.72 19.66,92.08 19.41,92.08 19.11,91.78 19.11,91.53 19.36,91.28 19.36,90.94 19.11,90.69 v2(19.11,90.33)
H_DDR1_D14: length 31.2
  TOP w0.102: U23.A3 v2(21.51,94.33)
  TOP w0.127: v1(36.58,87.35) 36.8,87.12 37.05,87.12 37.14,87.03 37.49,87.03 37.58,87.12 37.95,87.12 38.07,87.24 U27.AA25
  LY4 w0.133: v2(21.51,94.33) 21.93,94.74 22.23,94.74 22.37,94.61 22.37,94.24 22.5,94.11 22.76,94.11 22.89,94.24 22.89,94.61 23.03,94.74 23.29,94.74 23.42,94.61 23.42,94.24 23.55,94.11 23.82,94.11 23.95,94.24 23.95,94.61 24.08,94.74 24.35,94.74 24.48,94.61 24.48,94.24 24.61,94.11 24.87,94.11 25.01,94.24 25.01,94.61 25.14,94.74 25.4,94.74 25.54,94.61 25.54,94.24 25.67,94.11 25.93,94.11 26.06,94.24 26.06,94.61 26.2,94.74 26.46,94.74 26.59,94.61 26.59,94.24 26.72,94.11 26.99,94.11 27.12,94.24 27.12,94.61 27.25,94.74 31.37,94.74 31.57,94.54 31.57,94.14 31.7,94.01 33.05,94.01 33.25,93.8 33.25,92.96 33.93,92.28 33.93,91.41 34.92,90.42 35.03,90.42 36.2,89.26 36.2,88.47 36.58,88.09 v1(36.58,87.35)
H_DDR1_D15: length 31.2
  TOP w0.102: U27.W24 42.06,85.62 42.06,85.62 40.97,85.62 ; U23.C2 v2(19.91,95.13)
  TOP w0.127: 40.97,85.62 38.12,85.62 37.99,85.49 v1(37.57,85.49)
  LY4 w0.133: v2(19.91,95.13) 20.31,95.53 33.45,95.53 34.92,94.06 34.92,92.46 37.85,89.53 37.85,85.77 v1(37.57,85.49)
H_DDR1_D16: length 39.3
  TOP w0.102: U29.F8 v2(17.51,75.31)
  TOP w0.127: U27.W23 v3(42.7,85.62)
  LY4 w0.133: v3(42.7,85.62) 39.11,85.6 38.26,84.75 37.12,84.75 36.58,85.29 28.7,85.29 28.5,85.09 22.44,85.09 21.74,84.39 17.21,84.39 14.99,82.17 14.99,77.47 15.44,77.01 15.44,75.99 15.73,75.7 17.12,75.7 v2(17.51,75.31)
H_DDR1_D17: length 44
  TOP w0.102: U29.H8 v2(15.91,75.31)
  TOP w0.127: v1(31.11,81.41) 31.11,83.15 31.5,83.54 32.49,83.54 32.77,83.27 33.27,83.27 33.86,83.86 37.76,83.86 37.77,83.85 38.12,83.85 38.13,83.86 39.01,83.86 39.79,84.64 U27.U25
  LY3 w0.133: v1(31.11,81.41) 30.91,81.2 30.91,79.93 30.61,79.63 30.18,79.63 29.9,79.91 29.9,80.39 29.67,80.62 26.42,80.62 26.24,80.44 26.24,79.86 26.03,79.65 25.51,79.65 25.23,79.93 25.23,80.35 25.07,80.52 24.51,80.52 24.23,80.24 24.23,79.73 23.83,79.32 22.73,79.32 22.48,79.07 19.46,79.07 19,79.53 15.98,79.53 15.65,79.2 15.65,76.84 15.81,76.68 16.12,76.68 16.28,76.84 16.28,78.94 16.43,79.1 16.74,79.1 16.89,78.94 16.89,76.94 16.31,76.37 16.31,75.71 v2(15.91,75.31)
H_DDR1_D18: length 44.5
  TOP w0.102: U29.F7 v2(17.51,76.11) ; 40.97,84.32 42.06,84.32 42.06,84.32 U27.U24
  TOP w0.127: 40.97,84.32 39.94,84.32 39.24,83.61 38.23,83.61 38.22,83.6 37.67,83.6 37.66,83.61 34.1,83.61 33.51,83.01 32.54,83.01 32.29,83.26 31.9,83.26 31.7,83.06 31.7,82.25 31.78,82.17 32,82.17 32.46,82.63 32.77,82.63 32.87,82.52 32.87,82.37 31.65,81.16 31.65,79.53 v1(31.11,78.99)
  LY3 w0.133: v2(17.51,76.11) 17.11,75.7 17.11,74.18 17.4,73.89 19.3,73.89 19.51,74.09 19.51,74.34 19.51,74.34 19.51,76.27 19.51,76.27 19.51,76.46 19.3,76.67 19.3,78 19.68,78.38 22.99,78.38 23.32,78.71 24.43,78.71 24.71,78.99 26.92,78.99 27.05,78.86 27.05,78.54 26.95,78.44 25.58,78.44 25.38,78.24 25.38,78.05 25.58,77.85 29.08,77.85 29.31,78.08 30.84,78.08 31.11,78.36 v1(31.11,78.99)
H_DDR1_D19: length 42.8
  TOP w0.102: U29.F2 v2(17.51,80.9)
  TOP w0.127: U27.W21 v3(44,85.62)
  LY3 w0.133: v2(17.51,80.9) 17.11,81.31 17.11,82.13 17.65,82.68 17.65,83.38 18.19,83.91 18.19,85.57 18.97,86.36 21.06,86.36 21.83,87.14 22.17,87.14 22.3,87.01 22.3,86.67 22.43,86.54 22.7,86.54 22.83,86.67 22.83,87.01 22.96,87.14 23.22,87.14 23.36,87.01 23.36,86.67 23.49,86.54 23.75,86.54 23.88,86.67 23.88,87.01 24.08,87.2 27.51,87.2 28.14,86.57 35.7,86.57 36.22,86.06 36.76,86.06 36.89,86.19 36.89,86.84 37.02,86.97 37.29,86.97 37.42,86.84 37.42,86.19 37.55,86.06 37.81,86.06 37.95,86.19 37.95,86.84 38.08,86.97 38.34,86.97 38.47,86.84 38.47,86.19 38.61,86.06 38.87,86.06 39,86.19 39,86.84 39.13,86.97 39.4,86.97 39.53,86.84 39.53,86.19 39.66,86.06 39.93,86.06 40.06,86.19 40.06,86.84 40.19,86.97 40.46,86.97 40.59,86.84 40.59,86.19 40.72,86.06 40.98,86.06 41.12,86.19 41.12,86.84 41.25,86.97 41.51,86.97 41.64,86.84 41.64,86.24 41.78,86.11 43.51,86.11 v3(44,85.62)
H_DDR1_D20: length 42.4
  TOP w0.102: U29.E3 v2(18.31,80.1)
  TOP w0.127: U27.T22 v3(43.35,83.67)
  LY3 w0.133: v3(43.35,83.67) 43.73,84.04 44.16,84.04 44.38,84.26 44.38,84.45 44.25,84.59 43.56,84.59 43.05,84.07 41.81,84.07 41.68,84.21 41.68,84.63 41.55,84.76 41.17,84.76 40.97,84.56 40.97,83.85 40.77,83.65 40.51,83.65 40.33,83.82 40.33,84.68 40.23,84.78 39.92,84.78 39.79,84.65 39.79,83.85 39.65,83.72 39.39,83.72 39.12,83.99 39.12,84.46 38.8,84.78 38.37,84.78 38.29,84.7 37.67,84.7 37.56,84.59 36.96,84.59 36.7,84.33 35.26,84.33 35.13,84.46 35.13,84.65 35.23,84.75 35.83,84.75 35.97,84.88 35.97,85.06 35.84,85.19 29.41,85.19 29.01,84.79 22.53,84.79 21.91,84.17 20.41,84.17 20.2,83.95 20.2,82.4 20.04,82.25 19.86,82.25 19.74,82.37 19.74,83.95 19.59,84.09 19.4,84.09 19.15,83.85 19.15,82.88 18.72,82.44 18.72,80.51 v2(18.31,80.1)
H_DDR1_D21: length 42.5
  TOP w0.102: U29.G2 v2(16.71,80.9)
  TOP w0.127: U27.U22 v3(43.35,84.97)
  LY3 w0.133: v3(43.35,84.97) 42.89,84.51 42.39,84.51 41.38,85.52 38.44,85.52 38.31,85.39 38.31,85.17 38.17,85.04 36.68,85.04 36.22,85.5 29.14,85.5 28.7,85.06 27.55,85.06 27.42,85.2 27.42,86.1 27.28,86.23 27.02,86.23 26.89,86.1 26.89,85.2 26.76,85.06 26.49,85.06 26.36,85.2 26.36,86.1 26.23,86.23 25.96,86.23 25.83,86.1 25.83,85.2 25.7,85.06 25.44,85.06 25.3,85.2 25.3,86.1 25.17,86.23 24.91,86.23 24.78,86.1 24.78,85.2 24.64,85.06 24.38,85.06 24.25,85.2 24.25,86.1 24.11,86.23 23.85,86.23 23.72,86.1 23.72,85.2 23.59,85.06 23.32,85.06 23.19,85.2 23.19,86.1 23.06,86.23 22.79,86.23 22.66,86.1 22.66,85.34 21.76,84.43 19.2,84.43 17.91,83.14 17.91,80.73 17.69,80.51 17.11,80.51 v2(16.71,80.9)
H_DDR1_D22: length 39.1
  TOP w0.102: U29.H7 v2(15.91,76.11)
  TOP w0.127: U27.U23 v3(42.7,84.97)
  LY4 w0.133: v3(42.7,84.97) 42.26,84.53 41.97,84.53 41.79,84.71 41.79,85.14 41.64,85.29 41.42,85.29 41.26,85.14 41.26,84.61 41.13,84.48 40.84,84.48 40.67,84.66 40.67,85.01 40.53,85.14 40.06,85.14 39.9,84.99 39.9,84.23 39.46,83.78 37.45,83.78 36.25,84.99 28.98,84.99 28.8,84.81 22.57,84.81 21.79,84.02 17.32,84.02 15.37,82.07 15.37,77.72 15.91,77.18 v2(15.91,76.11)
H_DDR1_D23: length 39.2
  TOP w0.102: U29.H3 v2(15.91,80.1)
  TOP w0.127: U27.T21 v3(44,83.67)
  LY4 w0.133: v2(15.91,80.1) 15.91,78.42 16.23,78.11 23.01,78.11 24.02,79.11 24.02,81.7 24.37,82.06 34,82.06 34.14,82.19 34.66,82.19 34.8,82.06 35.06,82.06 35.19,82.19 35.19,82.62 35.32,82.75 35.59,82.75 35.72,82.62 35.72,82.19 35.85,82.06 36.12,82.06 36.25,82.19 36.25,82.62 36.38,82.75 36.65,82.75 36.78,82.62 36.78,82.19 36.91,82.06 37.17,82.06 37.31,82.19 37.31,82.62 37.44,82.75 37.7,82.75 37.83,82.62 37.83,82.19 37.97,82.06 39.23,82.06 39.42,82.24 39.42,82.43 39.24,82.61 39.24,82.8 39.43,82.99 39.61,82.99 39.79,82.81 39.98,82.81 41.25,84.07 43.6,84.07 v3(44,83.67)
H_DDR1_D24: length 31.3
  TOP w0.102: U29.C3 v2(19.91,80.1)
  TOP w0.127: U27.T23 v3(42.7,83.67)
  LY3 w0.133: v2(19.91,80.1) 19.51,80.5 19.51,81.09 19.73,81.3 20.94,81.3 21.11,81.47 21.11,81.92 21.34,82.14 21.72,82.14 21.84,82.27 21.84,82.66 21.71,82.8 21.32,82.8 21.11,83.01 21.11,83.52 21.49,83.9 23.08,83.9 23.63,84.45 29.13,84.45 29.49,84.81 32.26,84.81 32.49,84.58 32.49,84.26 32.62,84.12 33.25,84.12 33.45,84.33 33.45,84.66 33.66,84.86 34.26,84.86 34.49,84.63 34.49,84 34.65,83.85 38.71,83.85 39.22,83.34 41,83.34 41.32,83.66 v3(42.7,83.67)
H_DDR1_D25: length 32.6
  TOP w0.102: U29.A7 v2(21.51,76.11)
  TOP w0.127: v1(32.26,80.01) 32.26,81.28 34.33,83.36 37.55,83.36 37.56,83.35 38.33,83.35 38.34,83.36 39.36,83.36 39.93,83.92 40.92,83.92 40.99,83.99 U27.T25
  LY3 w0.133: v2(21.51,76.11) 21.84,76.43 23.3,76.43 23.44,76.56 23.44,77.01 23.57,77.14 23.83,77.14 23.96,77.01 23.96,76.56 24.1,76.43 24.36,76.43 24.49,76.56 24.49,77.01 24.63,77.14 24.89,77.14 25.02,77.01 25.02,76.56 25.15,76.43 25.42,76.43 25.55,76.56 25.55,77.01 25.68,77.14 25.95,77.14 26.08,77.01 26.08,76.56 26.21,76.43 26.47,76.43 26.61,76.56 26.61,77.01 26.74,77.14 27,77.14 27.13,77.01 27.13,76.56 27.27,76.43 27.53,76.43 27.66,76.56 27.66,77.01 27.8,77.14 28.06,77.14 28.19,77.01 28.19,76.56 28.32,76.43 28.59,76.43 28.72,76.56 28.72,77.01 28.85,77.14 29.12,77.14 29.25,77.01 29.25,76.56 29.38,76.43 30.58,76.43 31.75,77.6 31.75,79.5 v1(32.26,80.01)
H_DDR1_D26: length 32.6
  TOP w0.102: U29.B8 v2(20.71,75.31) ; U27.T24 42.06,83.67 40.97,83.67
  TOP w0.127: v1(32.25,79.13) 32.77,79.65 32.77,81.43 34.44,83.1 37.45,83.1 37.45,83.09 38.43,83.09 38.44,83.1 39.51,83.1 40.08,83.67 40.97,83.67
  LY3 w0.133: v1(32.25,79.13) 32.25,77.33 29.82,74.9 29.41,74.9 29.28,75.04 29.28,75.2 29.15,75.34 28.88,75.34 28.75,75.2 28.75,75.04 28.61,74.9 28.35,74.9 28.21,75.04 28.21,75.2 28.08,75.34 27.81,75.34 27.68,75.2 27.68,75.04 27.55,74.9 27.28,74.9 27.15,75.04 27.15,75.2 27.01,75.34 26.75,75.34 26.61,75.2 26.61,75.04 26.48,74.9 26.21,74.9 26.08,75.04 26.08,75.2 25.95,75.34 25.68,75.34 25.55,75.2 25.55,75.04 25.41,74.9 25.15,74.9 25.01,75.04 25.01,75.2 24.88,75.34 24.61,75.34 24.48,75.2 24.48,74.53 24.35,74.39 24.08,74.39 23.95,74.53 23.95,75.2 23.81,75.34 23.55,75.34 23.41,75.2 23.41,75.04 23.28,74.9 21.12,74.9 v2(20.71,75.31)
H_DDR1_D27: length 31.2
  TOP w0.102: U29.A3 v2(21.51,80.1)
  TOP w0.127: U27.P21 v3(44,83.02)
  LY3 w0.133: v2(21.51,80.1) 22.18,80.1 23.83,81.75 23.83,82.12 24.26,82.55 26.03,82.55 26.16,82.68 26.16,82.87 25.99,83.04 24.08,83.04 23.95,83.17 23.95,83.36 24.08,83.49 28.68,83.49 28.85,83.31 28.85,82.78 29.13,82.5 33.83,82.5 34.29,82.96 38.05,82.96 38.65,82.36 43.34,82.36 v3(44,83.02)
H_DDR1_D28: length 27.9
  TOP w0.102: U29.C8 v2(19.91,75.31)
  TOP w0.127: U27.N21 v3(44,81.72)
  LY4 w0.133: v2(19.91,75.31) 20.59,75.7 21.63,75.7 22.98,76.2 31.24,76.2 36.58,81.53 39.62,81.53 40.13,82.04 43.15,82.04 43.2,82.09 43.51,82.09 43.56,82.04 43.68,82.04 v3(44,81.72)
H_DDR1_D29: length 31.3
  TOP w0.102: U29.C2 v2(19.91,80.9)
  TOP w0.127: U27.P22 v3(43.35,83.02)
  LY3 w0.133: v3(43.35,83.02) 42.96,82.62 38.92,82.62 38.28,83.26 34.09,83.26 33.81,82.98 29.49,82.98 29.36,83.11 29.36,83.26 29.49,83.39 30.86,83.39 31.01,83.54 31.01,83.69 30.87,83.83 23.86,83.83 23.5,83.46 23.5,81.87 22.13,80.5 20.31,80.5 v2(19.91,80.9)
H_DDR1_D30: length 31.3
  TOP w0.102: U29.A2 v2(21.51,80.9)
  TOP w0.127: U27.P23 v3(42.7,83.02)
  LY3 w0.133: v2(21.51,80.9) 22.13,80.9 23.16,81.94 23.16,83.08 23.03,83.21 22.79,83.21 22.66,83.08 22.66,82.13 22.49,81.97 22.3,81.97 22.15,82.12 22.15,83.2 22.57,83.62 23.19,83.62 23.72,84.15 29.46,84.15 29.79,84.48 31.98,84.48 32.13,84.33 32.13,84 32.03,83.9 31.52,83.9 31.42,83.79 31.42,83.39 31.57,83.24 33.56,83.24 33.88,83.57 38.51,83.57 39,83.07 v3(42.7,83.02)
H_DDR1_D31: length 29.2
  TOP w0.102: 40.97,82.15 41.18,82.37 42.06,82.37 U27.P24 ; U29.D7 v2(19.11,76.11)
  TOP w0.127: v1(34.02,80.62) 34.54,81.15 35.05,81.15 35.69,81.79 40.6,81.79 40.97,82.15
  LY4 w0.133: v1(34.02,80.62) 30.21,80.62 29.84,80.26 29.84,79.88 29.59,79.63 28.26,79.63 28.07,79.82 28.07,80.26 27.61,80.72 25.73,80.72 25.25,80.24 25.25,79.53 24.31,78.59 24.31,78.11 23.65,77.44 19.56,77.44 19.11,77 v2(19.11,76.11)
H_DDR1_DQM0: length 33.4
  TOP w0.102: U23.E7 v2(18.31,90.33)
  TOP w0.127: v1(40.72,91.72) 42.01,91.72 43.03,90.7 U27.AE23
  LY3 w0.133: v1(40.72,91.72) 42.04,91.72 42.19,91.57 42.19,90.89 42.06,90.75 40.74,90.75 39.98,89.99 39.98,89.15 39.62,88.8 38.96,88.8 38.23,89.53 37.49,89.53 37.06,89.1 36.02,89.1 34.16,90.96 18.47,90.96 18.31,90.8 v2(18.31,90.33)
H_DDR1_DQM1: length 30.7
  TOP w0.102: U23.D3 v2(19.11,94.33)
  TOP w0.127: U27.W22 v3(43.35,85.62)
  LY4 w0.133: v2(19.11,94.33) 19.11,93.89 19.76,93.24 29.29,93.24 33.78,88.75 33.78,88.52 34.19,88.11 35.36,88.11 36.02,87.45 36.02,86.44 37.4,85.05 37.92,85.05 38.99,86.12 42.85,86.12 v3(43.35,85.62)
H_DDR1_DQM2: length 42.4
  TOP w0.102: U29.E7 v2(18.31,76.11)
  TOP w0.127: U27.U21 v3(44.65,84.97)
  LY3 w0.133: v2(18.31,76.11) 18.31,76.76 18.11,76.96 17.49,76.96 17.35,77.1 17.35,77.37 17.54,77.56 18.3,77.56 18.45,77.71 18.45,77.95 18.31,78.08 17.48,78.08 17.3,78.26 17.3,79.07 17.4,79.17 18.8,79.17 19.28,78.69 22.63,78.69 22.96,79.02 24.13,79.02 24.38,79.27 26.34,79.27 26.59,79.53 28.57,79.53 28.7,79.39 28.7,79.15 28.6,79.04 27.64,79.04 27.51,78.91 27.51,78.64 27.64,78.51 28.91,78.51 29.33,78.93 30.43,78.93 31.37,79.87 31.37,80.39 32.19,81.21 38.29,81.21 39.17,82.1 41.08,82.1 41.1,82.12 44.28,82.12 45.03,82.86 45.03,83.82 44.83,84.02 44.83,84.79 v3(44.65,84.97)
H_DDR1_DQM3: length 32.1
  TOP w0.102: U29.D3 v2(19.11,80.1)
  TOP w0.127: v1(34.69,81.64) 35.23,82.17 40.46,82.17 40.98,82.69 U27.P25
  LY3 w0.133: v2(19.11,80.1) 19.79,79.43 22.2,79.43 24.82,82.04 34.09,82.04 34.54,82.5 37.66,82.5 37.8,82.37 37.8,81.76 37.67,81.64 v1(34.69,81.64)
H_DDR1_DQS0_N: length 33.4
  TOP w0.102: v1(41.2,92.89) 41.43,92.66 42.11,92.66 43.68,91.09 43.68,90.12 43.68,90.12 43.68,89.85 U27.AE22
  TOP w0.103: U23.G3 v2(16.71,94.33)
  LY3 w0.102: v1(41.2,92.89) 41.43,92.66 41.63,92.66 41.73,92.76
  LY3 w0.114: v2(16.71,94.33) 16.92,94.13 16.92,93.32 17.58,92.66 23.75,92.66 24.26,92.15 34.36,92.15 35.53,93.32 38.71,93.32 38.96,93.07 39.24,93.07 39.5,93.32 40.18,93.32 40.46,93.04 40.74,93.04 41.02,93.32 41.48,93.32 41.73,93.07 41.73,92.76
H_DDR1_DQS0_P: length 33.7
  TOP w0.102: v1(41.22,92.15) 41.45,92.38 41.93,92.38 43.35,90.95 43.35,90.12
  TOP w0.103: U23.F3 v2(17.51,94.33) ; U27.AD22 43.68,89.37 43.35,89.7 43.35,90.12
  LY3 w0.102: v1(41.22,92.15) 41.22,92.18 41.43,92.38 41.81,92.38
  LY3 w0.114: 41.81,92.38 42.04,92.61 42.04,93.27 41.63,93.68 35.38,93.68 34.21,92.51 24.41,92.51 23.9,93.01 17.72,93.01 17.27,93.47 17.27,94.09 v2(17.51,94.33)
H_DDR1_DQS1_N: length 31.3
  TOP w0.103: U23.B7 v2(20.71,90.33)
  TOP w0.112: v1(35.48,86.15) 35.7,86.36 36.89,86.36 36.94,86.41 38.27,86.41 38.43,86.56 41.7,86.56 U27.Y25
  LY4 w0.114: v2(20.71,90.33) 20.42,90.62 20.42,90.75 20.6,90.93 21.82,90.93 22.37,90.39 26.48,90.39 27.57,89.3 27.57,88.43 26.92,87.78 26.21,87.78 25.6,87.17 25.6,86.16 26.19,85.57 27.38,85.57 28.29,86.49 28.65,86.49 29.01,86.13 29.31,86.13 29.67,86.49 29.95,86.49 30.22,86.21 30.38,86.21 30.66,86.49 30.86,86.49 31.14,86.21 31.3,86.21 31.57,86.49 34.7,86.49 34.77,86.42 34.93,86.42 35,86.49 35.14,86.49 v1(35.48,86.15)
H_DDR1_DQS1_P: length 31.8
  TOP w0.103: U23.C7 v2(19.91,90.33)
  TOP w0.112: v1(35.48,87.03) 35.8,86.72 36.74,86.72 36.79,86.76 38.12,86.76 38.28,86.92 41.55,86.92 41.57,86.93 41.89,86.93 41.91,86.92 42.05,86.92 U27.Y24
  LY4 w0.114: v1(35.48,87.03) 35.3,86.84 28.14,86.84 27.23,85.93 26.34,85.93 25.96,86.31 25.96,87.03 26.36,87.43 27.07,87.43 27.93,88.29 27.93,89.44 26.63,90.74 22.51,90.74 21.97,91.29 20.45,91.29 20.07,90.9 20.07,90.48 v2(19.91,90.33)
H_DDR1_DQS2_N: length 40.3
  TOP w0.102: U27.V25 41.72,85.3 41.29,85.3 41.29,85.31 41,85.31 40.97,85.28
  TOP w0.103: U29.G3 v2(16.71,80.1)
  TOP w0.112: v1(32.94,84.57) 33.71,84.57 33.83,84.68 37.11,84.68 37.48,85.05 38.19,85.05 38.39,85.26 40.94,85.26 40.97,85.28
  LY4 w0.114: v1(32.94,84.57) 33.67,84.57 34.29,83.95 34.29,83.15 33.74,82.6 30.99,82.6 30.67,82.92 30.67,83.53 30.55,83.64 30.33,83.64 30.21,83.53 30.21,82.92 29.89,82.6 29.36,82.6 29.04,82.92 29.04,83.53 28.93,83.64 28.7,83.64 28.59,83.53 28.59,82.92 28.26,82.6 27.74,82.6 27.42,82.92 27.42,83.53 27.3,83.64 27.07,83.64 26.96,83.53 26.96,82.92 26.64,82.6 26.11,82.6 25.79,82.92 25.79,83.53 25.6,83.72 24.66,83.72 22.99,82.04 22.99,79.38 22.25,78.64 17.12,78.64 16.71,79.05 v2(16.71,80.1)
H_DDR1_DQS2_P: length 40.5
  TOP w0.102: 41.86,84.95 41.88,84.95 41.88,84.95 41.89,84.95 41.9,84.96 42.05,84.96 42.06,84.97
  TOP w0.103: U29.F3 v2(17.51,80.1) ; U27.V24 42.06,84.97
  TOP w0.112: v1(32.94,83.68) 32.94,84.02 33.08,84.15 33.11,84.15 33.17,84.21 33.86,84.21 33.98,84.33 37.26,84.33 37.62,84.69 38.33,84.69 38.54,84.9 41.09,84.9 41.14,84.95 41.86,84.95
  LY4 w0.114: v2(17.51,80.1) 17.24,80.1 17.07,79.93 17.07,79.19 17.27,78.99 22.1,78.99 22.63,79.53 22.63,82.19 24.52,84.07 25.75,84.07 26.15,83.68 26.15,83.07 26.26,82.96 26.49,82.96 26.6,83.07 26.6,83.68 26.93,84 27.45,84 27.77,83.68 27.77,83.07 27.89,82.96 28.12,82.96 28.23,83.07 28.23,83.68 28.55,84 29.08,84 29.4,83.68 29.4,83.07 29.51,82.96 29.74,82.96 29.86,83.07 29.86,83.68 30.18,84 30.7,84 31.02,83.68 31.02,83.07 31.14,82.96 33.59,82.96 33.93,83.3 33.93,83.8 33.52,84.21 33.16,84.21 32.94,84 v1(32.94,83.68)
H_DDR1_DQS3_N: length 29.6
  TOP w0.102: 40.97,83.34 41.73,83.34 U27.R25
  TOP w0.103: U29.B7 v2(20.71,76.11)
  TOP w0.112: v1(30.25,78.51) 30.5,78.26 32.11,78.26 33.17,79.32 33.17,81.2 34.82,82.85 39.95,82.85 40.44,83.34 40.97,83.34
  LY4 w0.114: v1(30.25,78.51) 30.5,78.26 31.21,78.26 31.6,77.88 31.6,77.14 31.09,76.63 20.61,76.63 20.5,76.52 20.5,76.32 v2(20.71,76.11)
H_DDR1_DQS3_P: length 29.8
  TOP w0.102: 40.97,82.98 41.11,82.98 41.15,83.02 42.06,83.02 U27.R24
  TOP w0.103: U29.C7 v2(19.91,76.11)
  TOP w0.112: v1(30.25,77.66) 30.5,77.91 32.26,77.91 33.53,79.18 33.53,81.05 34.97,82.49 40.09,82.49 40.58,82.98 40.97,82.98
  LY4 w0.114: v2(19.91,76.11) 20.14,76.33 20.14,76.66 20.46,76.99 30.94,76.99 31.24,77.29 31.24,77.73 31.07,77.91 30.5,77.91 v1(30.25,77.66)
H_DDR1_ODT0: length 103.1
  TOP w0.102: 46.6,90.58 46.6,89.51 U27.AD18 ; U29.K1 v2(13.51,81.7) ; U23.K1 v2(13.51,95.93)
  TOP w0.127: v1(45.57,96.32) 45.57,94.21 45.68,94.09 45.68,92.75 46.6,91.83 46.6,90.58
  LY3 w0.133: v1(45.57,96.32) 45.57,95.33 45.34,95.1 43.64,95.1 42.29,96.45 42.29,97.06 41.73,97.63 40.2,97.63 39.59,98.24 38.63,98.24 38.5,98.11 38.5,97.13 38.37,96.99 38.1,96.99 37.97,97.13 37.97,98.11 37.83,98.24 37.57,98.24 37.43,98.11 37.43,97.13 37.3,96.99 37.03,96.99 36.9,97.13 36.9,98.11 36.77,98.24 36.5,98.24 36.37,98.11 36.37,97.13 36.23,96.99 35.97,96.99 35.83,97.13 35.83,98.11 35.7,98.24 35.43,98.24 35.3,98.11 35.3,97.13 35.17,96.99 34.9,96.99 34.77,97.13 34.77,97.91 34.5,98.17 33.37,98.17 33.24,98.04 33.24,97.13 33.1,96.99 32.84,96.99 32.7,97.13 32.7,98.04 32.57,98.17 32.3,98.17 32.17,98.04 32.17,97.13 32.04,96.99 31.77,96.99 31.64,97.13 31.64,98.04 31.5,98.17 31.24,98.17 31.1,98.04 31.1,97.13 30.97,96.99 30.7,96.99 30.57,97.13 30.57,98.04 30.44,98.17 30.17,98.17 30.04,98.04 30.04,97.13 29.9,96.99 29.64,96.99 29.5,97.13 29.5,98.04 29.37,98.17 26.25,98.17 26.12,98.04 26.12,97.46 25.98,97.33 25.72,97.33 25.58,97.46 25.58,98.04 25.45,98.17 25.18,98.17 25.05,98.04 25.05,97.46 24.92,97.33 24.65,97.33 24.52,97.46 24.52,98.04 24.38,98.17 24.12,98.17 23.98,98.04 23.98,97.46 23.85,97.33 23.58,97.33 23.45,97.46 23.45,98.04 23.32,98.17 23.05,98.17 22.92,98.04 22.92,97.46 22.78,97.33 22.52,97.33 22.38,97.46 22.38,98.04 22.25,98.17 16.23,98.17 16.09,98.04 16.09,97.34 15.96,97.21 15.69,97.21 15.56,97.34 15.56,98.04 15.43,98.17 15.16,98.17 15.03,98.04 15.03,97.34 14.89,97.21 14.63,97.21 14.49,97.34 14.49,98.04 14.36,98.17 13.98,98.17 13.51,97.7 v2(13.51,95.93)
  LY4 w0.133: v2(13.51,95.93) 13.92,95.26 13.92,91.9 14.76,91.06 14.76,88.95 13.51,87.71 13.51,87.45 13.65,87.31 14.04,87.31 14.17,87.18 14.17,86.91 14.04,86.78 13.65,86.78 13.51,86.64 v2(13.51,81.7) 13.91,81.31 13.91,77.34 14.73,76.52 14.73,75.44 14.99,75.18 14.99,72.9 15.61,72.28 17.36,72.28 18.92,70.72 v1(18.92,70.36)
  BOTTOM w0.127: R276.2 v1(18.92,70.36)
H_DDR1_RASN: length 109.8
  TOP w0.102: U23.J3 v2(14.31,94.33) ; U29.J3 v2(14.31,80.1) ; U27.AD17 47.25,89.51 47.25,90.29 47.21,90.34 47.21,90.58
  TOP w0.127: v1(44.88,98.83) 44.88,97.49 45.36,97 46.18,97 46.84,96.34 46.84,95.33 46.3,94.79 46.3,93.07 47.21,92.16 47.21,90.58 ; R96.2 v1(19.56,69.91)
  LY4 w0.133: v2(14.31,80.1) 14.31,77.48 15.18,76.61 15.18,75.62 15.49,75.31 15.49,73.96 16.92,72.54 17.53,72.54 19.56,70.51 v1(19.56,69.91)
  BOTTOM w0.127: v1(44.88,98.83) 44.26,98.83 43.79,99.3 42.01,99.3 41.94,99.23 40.83,99.23 40.7,99.1 40.7,98.48 40.57,98.35 40.32,98.35 40.19,98.22 40.19,97.61 40.07,97.48 39.81,97.48 39.68,97.61 39.68,98.22 39.56,98.35 39.3,98.35 39.18,98.22 39.18,97.61 39.05,97.48 38.8,97.48 38.67,97.61 38.67,98.22 38.54,98.35 38.29,98.35 38.16,98.22 38.16,97.61 38.03,97.48 37.78,97.48 37.65,97.61 37.65,98.22 37.53,98.35 37.27,98.35 37.14,98.22 37.14,97.61 37.02,97.48 36.76,97.48 36.64,97.61 36.64,98.22 36.51,98.35 36.26,98.35 36.13,98.22 36.13,97.61 36,97.48 35.75,97.48 35.62,97.61 35.62,98.22 35.49,98.35 35.24,98.35 35.11,98.22 35.11,97.61 34.99,97.48 34.73,97.48 34.6,97.61 34.6,98.22 34.48,98.35 34.22,98.35 34.1,98.22 34.1,97.61 33.97,97.48 33.72,97.48 33.59,97.61 33.59,98.22 33.46,98.35 33.21,98.35 33.08,98.22 33.08,97.61 32.95,97.48 32.7,97.48 32.57,97.61 32.57,98.22 32.45,98.35 32.19,98.35 32.06,98.22 32.06,97.61 31.94,97.48 31.68,97.48 31.56,97.61 31.56,98.22 31.43,98.35 31.18,98.35 31.05,98.22 31.05,97.61 30.92,97.48 30.67,97.48 30.54,97.61 30.54,98.22 30.41,98.35 30.16,98.35 30.03,98.22 30.03,97.61 29.91,97.48 29.65,97.48 29.52,97.61 29.52,98.22 29.4,98.35 29.14,98.35 29.02,98.22 29.02,97.61 28.89,97.48 28.64,97.48 28.51,97.61 28.51,98.22 28.38,98.35 28.13,98.35 28,98.22 28,97.61 27.87,97.48 27.62,97.48 27.49,97.61 27.49,98.22 27.37,98.35 27.11,98.35 26.98,98.22 26.98,97.61 26.86,97.48 26.6,97.48 26.48,97.61 26.48,98.22 26.35,98.35 26.1,98.35 25.97,98.22 25.97,97.61 25.84,97.48 25.59,97.48 25.46,97.61 25.46,98.22 25.33,98.35 25.08,98.35 24.95,98.22 24.95,97.61 24.83,97.48 24.57,97.48 24.44,97.61 24.44,98.22 24.32,98.35 24.06,98.35 23.94,98.22 23.94,97.61 23.81,97.48 23.56,97.48 23.43,97.61 23.43,98.22 23.3,98.35 23.05,98.35 22.92,98.48 22.92,99.1 22.39,99.63 17.09,99.63 16.71,99.25 16.71,97.07 16.3,96.66 15.09,96.66 14.71,96.28 14.71,94.73 v2(14.31,94.33) 15.37,93.27 18.39,93.27 18.82,92.84 18.82,91.69 18.44,91.31 15.52,91.31 14.96,90.75 14.96,88.9 14.71,88.65 14.71,85.01 15.49,84.23 15.49,81.89 14.84,81.24 14.84,80.64 v2(14.31,80.1)
H_DDR1_RST: length 74.6
  TOP w0.102: U23.T2 v2(8.71,95.13) ; U29.T2 v2(8.71,80.9)
  TOP w0.127: U27.AE17 46.93,91.98 45.99,92.93 45.99,94.91 46.58,95.5 46.58,96.21 46.05,96.75 45.24,96.75 44.42,97.56 v1(44.42,99.62)
  LY3 w0.133: v2(8.71,80.9) 7.08,80.9 6.45,81.53 6.45,93.45 6.83,93.83 8.89,93.83 9.12,94.05 9.12,94.73 v2(8.71,95.13) 9.12,95.53 9.12,101.11 10.33,102.33 39.27,102.33 41.18,100.41 43.03,100.41 43.82,99.62 v1(44.42,99.62)
H_DDR1_WEN: length 111.7
  TOP w0.102: U23.L3 v2(12.71,94.33) ; U29.L3 v2(12.71,80.1)
  TOP w0.127: v1(43.74,100.74) 43.74,97.84 45.15,96.43 45.15,94.27 45.43,93.99 45.43,92.64 46.28,91.79 U27.AE18
  BOTTOM w0.127: v1(43.74,100.74) 43.31,100.74 43.12,100.55 40.08,100.55 39.95,100.43 39.95,99.55 39.83,99.42 39.57,99.42 39.45,99.55 39.45,100.43 39.32,100.55 39.06,100.55 38.94,100.43 38.94,99.55 38.81,99.42 38.56,99.42 38.43,99.55 38.43,100.43 38.3,100.55 38.05,100.55 37.92,100.43 37.92,99.55 37.79,99.42 37.54,99.42 37.41,99.55 37.41,100.43 37.29,100.55 37.03,100.55 36.91,100.43 36.91,99.55 36.78,99.42 36.52,99.42 36.4,99.55 36.4,100.43 36.27,100.55 36.02,100.55 35.89,100.43 35.89,99.55 35.76,99.42 35.51,99.42 35.38,99.55 35.38,100.43 35.25,100.55 16.12,100.55 15.99,100.43 15.99,99.48 15.86,99.35 15.61,99.35 15.48,99.48 15.48,100.43 15.35,100.55 15.1,100.55 14.97,100.43 14.97,99.48 14.85,99.35 14.59,99.35 14.46,99.48 14.46,100.43 14.34,100.55 13.45,100.55 13.11,100.21 13.11,99.1 13.23,98.97 15.65,98.97 15.78,98.84 15.78,98.59 15.65,98.46 13.23,98.46 13.11,98.34 13.11,98.08 13.23,97.96 15.65,97.96 15.78,97.83 15.78,97.57 15.65,97.45 13.23,97.45 13.11,97.32 13.11,94.72 v2(12.71,94.33) 12.71,93.65 12.84,93.52 13.64,93.52 13.77,93.4 13.77,93.14 13.64,93.02 12.84,93.02 12.71,92.89 12.71,92.64 12.84,92.51 14.65,92.51 14.78,92.38 14.78,92.13 14.65,92 12.84,92 12.71,91.87 12.71,91.05 13.11,90.65 13.11,90.02 12.71,89.62 12.71,88.44 13.39,87.77 13.39,87.52 13.26,87.39 12.67,87.39 12.55,87.26 12.55,87.01 12.67,86.88 13.26,86.88 13.39,86.75 13.39,82.22 13.11,81.94 13.11,80.5 v2(12.71,80.1) 12.71,78.85 11.52,77.66 11.52,74.34 14.81,71.05 16.1,71.05 16.21,70.94 17.2,70.94 v1(17.78,70.36) R277.2
